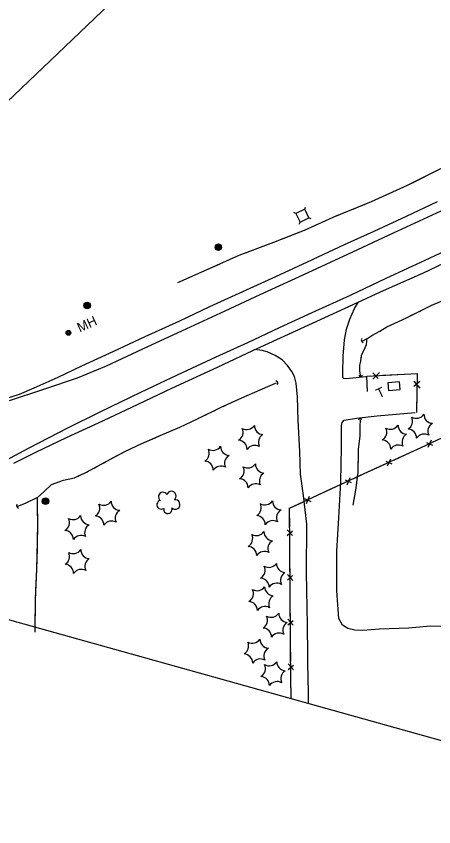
# Model space of a CAD drawing. Extents: x 588843 to 2552415, y 180129 to 269402.
# Drawn here: x 592527 to 592788, y 187391 to 187898 of the extents above; entities that cross this region are included whole.
import ezdxf

# ---------------------------------------------------------------- set-up
doc = ezdxf.new("R2010")
doc.units = 0
for name, color, linetype in [('Default', 7, 'Continuous'), ('Level 11', 7, 'Continuous'), ('Level 12', 7, 'Continuous'), ('Level 14', 7, 'Continuous'), ('Level 15', 7, 'Continuous'), ('Level 16', 7, 'Continuous'), ('Level 17', 7, 'Continuous'), ('Level 18', 7, 'Continuous'), ('Level 19', 7, 'Continuous'), ('Level 21', 7, 'Continuous')]:
    doc.layers.add(name, color=color, linetype=linetype)

msp = doc.modelspace()

# ---------------------------------------------------------------- linework, layer by layer
at = {"layer": 'Default'}
msp.add_lwpolyline([(592409.33, 187552.38), (592387.7, 187602.85), (592346.9, 187678.64), (592735.79, 188050.05), (592838.09, 187808.48), (592884.47, 187677.08), (592985.3, 187391.41)], close=True, dxfattribs=at)
at = {"layer": 'Level 11'}
for points in [[(593081.4, 187910.28), (593054.72, 187898.04), (593032.93, 187887.88), (593004.81, 187874.85), (592982.82, 187864.63), (592962.98, 187855.52), (592937.9, 187843.87), (592916.36, 187833.91), (592892.32, 187822.84), (592869.04, 187811.99), (592843.71, 187800.23), (592817.43, 187788), (592792.4, 187776.51), (592762.63, 187762.69), (592737.11, 187750.77), (592703.8, 187735.36), (592679.17, 187724.03), (592657.28, 187713.81), (592635.69, 187703.85), (592608.86, 187691.51), (592583.03, 187679.54), (592565.01, 187672.08), (592544.46, 187665.17), (592522.46, 187657.87)], [(592790.02, 187782.2), (592770.72, 187773.19), (592750.4, 187763.71), (592731.9, 187755.36), (592708.8, 187744.5), (592688.96, 187735.44), (592668.31, 187725.95), (592647.62, 187716.59), (592629.05, 187707.7), (592607.32, 187697.87), (592587.63, 187688.67), (592567.61, 187679.47), (592552.94, 187672.47), (592537.86, 187665.78), (592528.74, 187661.72), (592511.95, 187656.49)], [(592803.8, 187755.51), (592782.31, 187745.59), (592757.96, 187734.29), (592735.74, 187723.77), (592711.77, 187712.81), (592691.35, 187703.51), (592671.38, 187694.12), (592651.73, 187685.13), (592627.53, 187673.78), (592604.63, 187663.09), (592579.07, 187650.63), (592558.91, 187640.74), (592534.73, 187628.16), (592510.85, 187615.49)], [(592811.6, 187751.96), (592781.25, 187737.74), (592754.34, 187725.75), (592740.03, 187719.04), (592711.94, 187706.22), (592674.62, 187689.19), (592652.49, 187678.72), (592623.87, 187665.51), (592599.01, 187653.58), (592578.16, 187643.9), (592558.05, 187634.73), (592538.92, 187625.58), (592525.21, 187618.61)]]:
    msp.add_lwpolyline(points, dxfattribs=at)
at = {"layer": 'Level 12'}
msp.add_lwpolyline([(592759.56, 187664.36), (592766.87, 187664.84), (592766.55, 187669.62), (592759.24, 187669.15)], close=True, dxfattribs=at)
at = {"layer": 'Level 14'}
for centre, radius in [((592653.25, 187753.96), 2.02), ((592653.24, 187753.97), 1.52), ((592653.26, 187753.94), 1.01), ((592653.26, 187753.95), 0.502), ((592571.25, 187717.43), 2.02), ((592571.24, 187717.44), 1.52), ((592571.26, 187717.4), 1.01), ((592571.26, 187717.41), 0.502), ((592545.22, 187595.05), 2.02), ((592545.21, 187595.06), 1.52), ((592545.23, 187595.03), 1.01), ((592545.23, 187595.04), 0.502)]:
    msp.add_circle(centre, radius, dxfattribs=at)
at = {"layer": 'Level 15'}
for p, q in [((592749.76, 187675.25), (592753.26, 187671.7)), ((592749.77, 187671.43), (592753.94, 187675.48)), ((592775.51, 187670.2), (592779.26, 187665.76)), ((592779.33, 187669.94), (592775.54, 187666.7)), ((592783.3, 187631.84), (592787.19, 187630.13)), ((592784.52, 187628.81), (592786.54, 187633.34)), ((592759.1, 187617.11), (592761.13, 187621.62)), ((592757.9, 187620.13), (592761.78, 187618.41)), ((592732.49, 187608.41), (592736.38, 187606.7)), ((592733.71, 187605.38), (592735.72, 187609.9)), ((592707.11, 187596.64), (592711, 187594.93)), ((592708.32, 187593.61), (592710.34, 187598.14)), ((592699.64, 187573.49), (592696.36, 187577.21)), ((592696.38, 187573.64), (592699.55, 187576.47)), ((592699.81, 187545.52), (592696.53, 187549.23)), ((592696.56, 187545.67), (592699.72, 187548.49)), ((592700.03, 187517.54), (592696.75, 187521.25)), ((592696.78, 187517.69), (592699.94, 187520.52)), ((592700.27, 187489.57), (592696.98, 187493.27)), ((592697.01, 187489.71), (592700.18, 187492.54))]:
    msp.add_line(p, q, dxfattribs=at)
for points in [[(592698.62, 187478.39), (592698.09, 187540.67), (592697.78, 187590.65), (592744.5, 187612.31), (592780.11, 187628.69), (592816.12, 187645.42), (592861.15, 187666.43), (592884.3, 187677.55)], [(592746.59, 187663.72), (592746.13, 187673.28), (592777.64, 187675), (592777.25, 187650.43)], [(592746.59, 187663.72), (592746.13, 187673.28), (592748.29, 187673.4)], [(592756.04, 187673.82), (592769.37, 187674.55)], [(592769.37, 187674.55), (592777.64, 187675), (592777.58, 187671.54)], [(592777.46, 187663.78), (592777.25, 187650.43)], [(592763.32, 187620.97), (592773.65, 187625.72)], [(592773.65, 187625.72), (592780.11, 187628.69), (592782.73, 187629.91)], [(592748.23, 187614.03), (592757.31, 187618.21)], [(592737.91, 187609.26), (592744.5, 187612.31), (592748.23, 187614.03)], [(592722.84, 187602.27), (592731.91, 187606.48)], [(592712.53, 187597.49), (592722.84, 187602.27)], [(592697.78, 187590.3), (592697.78, 187590.65), (592706.53, 187594.71)], [(592697.86, 187578.93), (592697.78, 187590.3)], [(592697.96, 187562.32), (592697.9, 187572.32)], [(592698.03, 187550.95), (592697.96, 187562.32)], [(592698.15, 187534.34), (592698.09, 187540.67), (592698.07, 187544.34)], [(592698.24, 187522.97), (592698.15, 187534.34)], [(592698.38, 187506.36), (592698.3, 187516.36)], [(592698.48, 187495), (592698.38, 187506.36)], [(592698.62, 187478.39), (592698.53, 187488.39)], [(592698.62, 187478.39), (592698.65, 187471.52)], [(592698.62, 187478.39), (592698.65, 187471.52)]]:
    msp.add_lwpolyline(points, dxfattribs=at)
for centre, radius, start, end in [((592744.29, 187695.88), 1.64, 149.2146, 255.4541), ((592742.11, 187674.65), 1.5, 222.6922, 328.9318), ((592688.89, 187668.74), 1.62, 331.0055, 77.2451), ((592741.98, 187645.19), 1.42, 39.7608, 146.0003), ((592528.67, 187592.28), 1.59, 148.3847, 254.6242)]:
    msp.add_arc(centre, radius, start, end, dxfattribs=at)
at = {"layer": 'Level 16'}
for centre, radius in [((592559.53, 187700.33), 1.5), ((592559.53, 187700.33), 1.22), ((592559.53, 187700.31), 0.968), ((592559.51, 187700.3), 0.605)]:
    msp.add_circle(centre, radius, dxfattribs=at)
at = {"layer": 'Level 17'}
for points in [[(592745.5, 187672.84), (592733.12, 187671.55), (592731.73, 187671.77), (592731.15, 187672.51), (592731.02, 187675.34), (592731.35, 187685.81), (592732.13, 187695.9), (592733.37, 187702.67), (592735.56, 187708.95), (592738.37, 187715.63), (592740.69, 187719.35)], [(592709.39, 187479.78), (592708.94, 187517.72), (592708.27, 187550.26), (592708.53, 187580.69), (592706.56, 187598.53), (592704.68, 187611.9), (592704.11, 187626.18), (592703.23, 187645.5), (592702.71, 187660.35), (592702.01, 187668.96), (592700.78, 187673.09), (592699.14, 187676.26), (592696.54, 187679.92), (592693.12, 187683.37), (592688.71, 187686.1), (592683.69, 187688.38), (592680.58, 187689.38), (592676.14, 187689.88)], [(592798.65, 187516.78), (592785.86, 187516.87), (592772.1, 187515.55), (592754.1, 187514.96), (592743.54, 187514.09), (592738.68, 187514.29), (592734.19, 187515.39), (592730.93, 187517.46), (592728.57, 187521.69), (592727.42, 187538.92), (592727.3, 187563.79), (592728.66, 187584.6), (592729.85, 187607.11), (592730.24, 187628.91), (592730.32, 187642.39), (592730.72, 187644.23), (592731.88, 187645.64), (592739.6, 187647.07), (592752.66, 187648.5), (592776.24, 187650.48)], [(592709.39, 187479.78), (592709.46, 187468.5)]]:
    msp.add_lwpolyline(points, dxfattribs=at)
at = {"layer": 'Level 18'}
for centre, radius, start, end in [((592769.01, 187645.14), 5.72, 300.2928, 26.0577), ((592776.99, 187652.62), 5.72, 240.2928, 326.0577), ((592787.46, 187649.46), 5.72, 180.2928, 266.0577), ((592671.03, 187645.57), 5.72, 240.2928, 326.0577), ((592681.5, 187642.41), 5.72, 180.2928, 266.0577), ((592752.85, 187638.29), 5.72, 300.2928, 26.0577), ((592760.83, 187645.77), 5.72, 240.2928, 326.0577), ((592771.31, 187642.61), 5.72, 180.2928, 266.0577), ((592789.96, 187638.8), 5.72, 120.2928, 206.0578), ((592663.05, 187638.09), 5.72, 300.2928, 26.0577), ((592684, 187631.76), 5.72, 120.2928, 206.0578), ((592773.8, 187631.95), 5.72, 120.2928, 206.0578), ((592771.5, 187634.48), 5.72, 0.2928, 86.0577), ((592781.98, 187631.32), 5.72, 60.2928, 146.0577), ((592665.55, 187627.43), 5.72, 0.2928, 86.0577), ((592755.35, 187627.63), 5.72, 0.2928, 86.0577), ((592641.87, 187625.08), 5.72, 300.2928, 26.0577), ((592649.85, 187632.56), 5.72, 240.2928, 326.0577), ((592660.32, 187629.4), 5.72, 180.2928, 266.0577), ((592676.02, 187624.27), 5.72, 60.2928, 146.0577), ((592765.82, 187624.47), 5.72, 60.2928, 146.0577), ((592662.82, 187618.75), 5.72, 120.2928, 206.0578), ((592644.36, 187614.42), 5.72, 0.2928, 86.0577), ((592654.84, 187611.26), 5.72, 60.2928, 146.0577), ((592663.66, 187614.04), 5.72, 300.2928, 26.0577), ((592671.64, 187621.53), 5.72, 240.2928, 326.0577), ((592682.11, 187618.36), 5.72, 180.2928, 266.0577), ((592684.6, 187607.71), 5.72, 120.2928, 206.0578), ((592666.15, 187603.39), 5.72, 0.2928, 86.0577), ((592676.62, 187600.22), 5.72, 60.2928, 146.0577), ((592618.57, 187597.83), 2.78, 26.4761, 234.2491), ((592623.93, 187598.28), 2.97, 303.5052, 164.7391), ((592581.47, 187598.21), 5.72, 240.2928, 326.0577), ((592591.95, 187595.05), 5.72, 180.2928, 266.0577), ((592617.59, 187592.86), 2.78, 103.1531, 304.1641), ((592626.31, 187592.93), 2.97, 221.156, 104.1293), ((592682.36, 187598.47), 5.72, 240.2928, 326.0577), ((592692.83, 187595.3), 5.72, 180.2928, 266.0577), ((592573.49, 187590.73), 5.72, 300.2928, 26.0577), ((592621.68, 187589.92), 2.61, 165.8612, 23.7938), ((592674.38, 187590.99), 5.72, 300.2928, 26.0577), ((592562.41, 187589.22), 5.72, 240.2928, 326.0577), ((592572.88, 187586.05), 5.72, 180.2928, 266.0577), ((592575.99, 187580.07), 5.72, 0.2928, 86.0577), ((592594.44, 187584.39), 5.72, 120.2928, 206.0578), ((592676.87, 187580.33), 5.72, 0.2928, 86.0577), ((592695.33, 187584.65), 5.72, 120.2928, 206.0578), ((592554.43, 187581.73), 5.72, 300.2928, 26.0577), ((592575.37, 187575.4), 5.72, 120.2928, 206.0578), ((592586.46, 187576.91), 5.72, 60.2928, 146.0577), ((592687.35, 187577.16), 5.72, 60.2928, 146.0577), ((592556.92, 187571.08), 5.72, 0.2928, 86.0577), ((592677, 187579.21), 5.72, 240.2928, 326.0577), ((592687.47, 187576.04), 5.72, 180.2928, 266.0577), ((592567.39, 187567.91), 5.72, 60.2928, 146.0577), ((592669.02, 187571.72), 5.72, 300.2928, 26.0577), ((592689.97, 187565.39), 5.72, 120.2928, 206.0578), ((592562.51, 187568), 5.72, 240.2928, 326.0577), ((592572.98, 187564.83), 5.72, 180.2928, 266.0577), ((592671.51, 187561.07), 5.72, 0.2928, 86.0577), ((592554.53, 187560.51), 5.72, 300.2928, 26.0577), ((592681.99, 187557.9), 5.72, 60.2928, 146.0577), ((592557.02, 187549.86), 5.72, 0.2928, 86.0577), ((592575.47, 187554.18), 5.72, 120.2928, 206.0578), ((592684.81, 187559.35), 5.72, 240.2928, 326.0577), ((592695.29, 187556.19), 5.72, 180.2928, 266.0577), ((592567.49, 187546.69), 5.72, 60.2928, 146.0577), ((592676.83, 187551.87), 5.72, 300.2928, 26.0577), ((592697.78, 187545.54), 5.72, 120.2928, 206.0578), ((592679.33, 187541.21), 5.72, 0.2928, 86.0577), ((592669.48, 187537.28), 5.72, 300.2928, 26.0577), ((592677.46, 187544.77), 5.72, 240.2928, 326.0577), ((592687.93, 187541.6), 5.72, 180.2928, 266.0577), ((592689.8, 187538.05), 5.72, 60.2928, 146.0577), ((592690.43, 187530.95), 5.72, 120.2928, 206.0578), ((592671.97, 187526.63), 5.72, 0.2928, 86.0577), ((592682.45, 187523.46), 5.72, 60.2928, 146.0577), ((592686.27, 187528.15), 5.72, 240.2928, 326.0577), ((592696.75, 187524.98), 5.72, 180.2928, 266.0577), ((592678.29, 187520.66), 5.72, 300.2928, 26.0577), ((592699.24, 187514.33), 5.72, 120.2928, 206.0578), ((592680.79, 187510.01), 5.72, 0.2928, 86.0577), ((592691.26, 187506.84), 5.72, 60.2928, 146.0577), ((592666.5, 187504.47), 5.72, 300.2928, 26.0577), ((592674.48, 187511.95), 5.72, 240.2928, 326.0577), ((592684.96, 187508.78), 5.72, 180.2928, 266.0577), ((592669, 187493.81), 5.72, 0.2928, 86.0577), ((592687.45, 187498.13), 5.72, 120.2928, 206.0578), ((592679.47, 187490.64), 5.72, 60.2928, 146.0577), ((592685, 187497.83), 5.72, 240.2928, 326.0577), ((592695.48, 187494.66), 5.72, 180.2928, 266.0577), ((592677.02, 187490.34), 5.72, 300.2928, 26.0577), ((592697.97, 187484.01), 5.72, 120.2928, 206.0578), ((592679.52, 187479.69), 5.72, 0.2928, 86.0577), ((592689.99, 187476.52), 5.72, 60.2928, 146.0577)]:
    msp.add_arc(centre, radius, start, end, dxfattribs=at)
at = {"layer": 'Level 19'}
for points in [[(592833.25, 187819.91), (592818.82, 187813.55), (592791.42, 187802.41), (592771.37, 187792.39), (592748.8, 187782.18), (592724.77, 187772.51), (592706.82, 187764.42), (592687.78, 187756.94), (592665.99, 187748.64), (592646.1, 187739.75), (592627.64, 187731.52)], [(592801.14, 187806.36), (592791.42, 187802.41), (592774.86, 187794.13)], [(592774.86, 187794.13), (592771.37, 187792.39), (592748.8, 187782.18), (592748.49, 187782.05)], [(592739.21, 187778.32), (592737.36, 187777.57)], [(592744.78, 187780.56), (592742.92, 187779.81)], [(592728.08, 187773.84), (592724.77, 187772.51), (592706.82, 187764.42), (592701.47, 187762.31)], [(592733.65, 187776.08), (592731.79, 187775.33)], [(592746.11, 187696.68), (592749.15, 187698.64), (592754.31, 187701.4), (592758.66, 187704.02), (592770.94, 187709.78), (592777.67, 187713.01), (592786.76, 187717.69), (592796.05, 187721.68), (592805.63, 187726.93), (592818.88, 187734.28), (592825.54, 187737.71), (592833.76, 187741.92), (592840.3, 187745.03), (592848.4, 187749.06), (592858.11, 187753.87), (592867.53, 187758.05), (592875.7, 187761.51), (592883.88, 187764.65), (592893.36, 187768.71), (592900.2, 187772.52), (592905.31, 187775.09), (592906.98, 187776.39)], [(592701.47, 187762.31), (592687.78, 187756.94), (592674.42, 187751.85)], [(592665.09, 187748.24), (592663.27, 187747.42)], [(592670.68, 187750.42), (592668.81, 187749.71)], [(592654.13, 187743.34), (592646.1, 187739.75), (592627.64, 187731.52)], [(592659.61, 187745.79), (592657.79, 187744.97)], [(592784.99, 187716.78), (592786.76, 187717.69), (592787, 187717.79)], [(592746.11, 187696.68), (592749.15, 187698.64), (592754.31, 187701.4), (592758.66, 187704.02), (592770.94, 187709.78), (592774.96, 187711.71)], [(592779, 187713.7), (592781, 187714.72)], [(592742.22, 187673.67), (592741.71, 187676.49), (592741.7, 187680.08), (592742.33, 187682.55), (592742.82, 187686.15), (592743.77, 187688.51), (592745.04, 187691.12), (592745.81, 187693.09), (592746.15, 187694.73), (592746.13, 187695.74), (592746.11, 187696.68), (592743.31, 187695.05)], [(592744.69, 187690.4), (592745.04, 187691.12), (592745.81, 187693.09), (592746.15, 187694.73), (592746.13, 187695.74), (592746.11, 187696.68), (592743.31, 187695.05)], [(592743.03, 187686.69), (592743.29, 187687.32)], [(592743.8, 187688.57), (592744.1, 187689.18)], [(592742.22, 187673.67), (592741.71, 187676.49), (592741.7, 187680.08), (592742.33, 187682.55), (592742.44, 187683.37)], [(592742.62, 187684.71), (592742.71, 187685.38)], [(592540.08, 187597.39), (592544.28, 187601.01), (592549.03, 187605.46), (592556.4, 187608.14), (592563.29, 187609.69), (592570.83, 187613.19), (592580.48, 187618.32), (592595.16, 187626.4), (592605.51, 187631.04), (592616.98, 187636.15), (592629.21, 187641.4), (592639.8, 187646.42), (592655, 187653.76), (592667.84, 187659.65), (592679.38, 187664.64), (592685.68, 187667.36), (592688.49, 187668.56), (592689.61, 187669.02)], [(592661.94, 187656.94), (592667.84, 187659.65), (592679.38, 187664.64), (592685.68, 187667.36), (592688.49, 187668.56), (592689.61, 187669.02)], [(592650.62, 187651.64), (592652.5, 187652.55)], [(592656.26, 187654.34), (592658.15, 187655.2)], [(592613.73, 187634.7), (592616.98, 187636.15), (592629.21, 187641.4), (592639.8, 187646.42), (592641.24, 187647.12)], [(592644.99, 187648.93), (592646.87, 187649.84)], [(592741.84, 187645.89), (592741.67, 187641.86), (592741.68, 187635.94), (592740.74, 187627.48), (592740.44, 187612.8), (592739.05, 187602), (592737.37, 187592.51)], [(592741.84, 187645.89), (592741.67, 187641.86), (592741.68, 187635.94), (592740.74, 187627.48), (592740.72, 187626.49)], [(592586.52, 187621.65), (592595.16, 187626.4), (592605.51, 187631.04), (592613.73, 187634.7)], [(592740.66, 187623.8), (592740.64, 187622.46)], [(592575.54, 187615.69), (592577.38, 187616.67)], [(592581.05, 187618.64), (592582.87, 187619.64)], [(592740.5, 187615.75), (592740.47, 187614.41)], [(592740.58, 187619.78), (592740.56, 187618.44)], [(592540.08, 187597.39), (592544.28, 187601.01), (592549.03, 187605.46), (592556.4, 187608.14), (592563.29, 187609.69), (592566.22, 187611.05)], [(592570, 187612.81), (592570.83, 187613.19), (592571.86, 187613.74)], [(592740.3, 187611.74), (592739.05, 187602), (592737.37, 187592.51)], [(592540.39, 187585.03), (592540.25, 187589.58), (592540.22, 187593.92), (592540.08, 187597.39), (592532.54, 187593.63), (592527.61, 187591.63)], [(592538.8, 187516.2), (592539, 187533.38), (592539.7, 187552.6), (592540.26, 187569.93), (592540.49, 187581.9), (592540.25, 187589.58), (592540.22, 187593.92), (592540.08, 187597.39), (592532.54, 187593.63), (592527.61, 187591.63)], [(592540.45, 187579.64), (592540.48, 187581.44)], [(592540.34, 187574.24), (592540.38, 187576.04)], [(592540.22, 187568.84), (592540.26, 187569.93), (592540.27, 187570.64)], [(592539.21, 187539.15), (592539.7, 187552.6), (592540.11, 187565.24)], [(592538.76, 187513.04), (592539, 187533.38), (592539.21, 187539.15)]]:
    msp.add_lwpolyline(points, dxfattribs=at)
at = {"layer": 'Level 21'}
for p, q in [((592707.23, 187777.63), (592707.75, 187779.04)), ((592701.8, 187775.08), (592700.39, 187775.6)), ((592703.83, 187768.24), (592704.34, 187769.65)), ((592711.19, 187771.68), (592709.78, 187772.19))]:
    msp.add_line(p, q, dxfattribs=at)
msp.add_lwpolyline([(592704.34, 187769.65), (592709.78, 187772.19), (592707.23, 187777.63), (592701.8, 187775.08)], close=True, dxfattribs=at)

# ---------------------------------------------------------------- texts
at = {"layer": 'Level 12'}
msp.add_text('T', height=6, rotation=25.0815, dxfattribs=at).set_placement((592753.66, 187659.2))
at = {"layer": 'Level 16'}
msp.add_text('MH', height=6, rotation=24.7399, dxfattribs=at).set_placement((592566.64, 187700.49))

doc.saveas('drawing.dxf')
